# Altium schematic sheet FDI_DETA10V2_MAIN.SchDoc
size A4
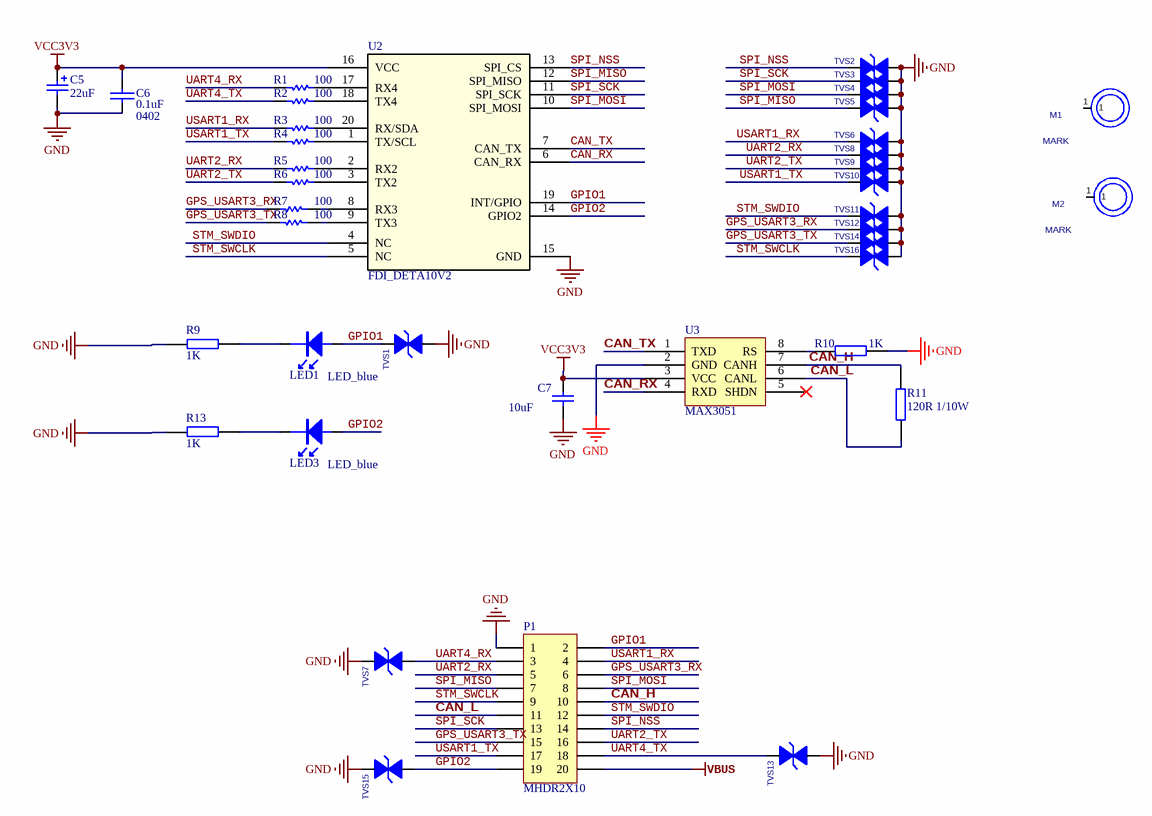
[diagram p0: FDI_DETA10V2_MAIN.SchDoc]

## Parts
C5  22uF  [C1206]
C6  Type: 0402  [C0402]  (hidden comment: 0.1uF)
C7  10uF  [C0603]
LED1  LED_blue  [LED_0603_BLUE]
LED3  LED_blue  [LED_0603_BLUE]
M1  MARK  [MARK_POINT]
M2  MARK  [MARK_POINT]
P1  MHDR2X10  [HEAD_2.54_20]
R1  100  [RES0402]
R2  100  [RES0402]
R3  100  [RES0402]
R4  100  [RES0402]
R5  100  [RES0402]
R6  100  [RES0402]
R7  100  [RES0402]
R8  100  [RES0402]
R9  1K  [RES0402]
R10  1K  [RES0402]
R11  120R 1/10W  [RES0603]
R13  1K  [RES0402]
TVS1  PTUC0521NC/5V  [ESD_0402]  (value not drawn)
TVS2  PTUC0521NC/5V  [ESD_0402]  (value not drawn)
TVS3  PTUC0521NC/5V  [ESD_0402]  (value not drawn)
TVS4  PTUC0521NC/5V  [ESD_0402]  (value not drawn)
TVS5  PTUC0521NC/5V  [ESD_0402]  (value not drawn)
TVS6  PTUC0521NC/5V  [ESD_0402]  (value not drawn)
TVS7  PTUC0521NC/5V  [ESD_0402]  (value not drawn)
TVS8  PTUC0521NC/5V  [ESD_0402]  (value not drawn)
TVS9  PTUC0521NC/5V  [ESD_0402]  (value not drawn)
TVS10  PTUC0521NC/5V  [ESD_0402]  (value not drawn)
TVS11  PTUC0521NC/5V  [ESD_0402]  (value not drawn)
TVS12  PTUC0521NC/5V  [ESD_0402]  (value not drawn)
TVS13  PTUC0521NC/5V  [ESD_0402]  (value not drawn)
TVS14  PTUC0521NC/5V  [ESD_0402]  (value not drawn)
TVS15  PTUC0521NC/5V  [ESD_0402]  (value not drawn)
TVS16  PTUC0521NC/5V  [ESD_0402]  (value not drawn)
U2  FDI_DETA10V2  [FDI_DETA]
U3  MAX3051  [SOT23-8]

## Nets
GND: C5.2 C6.1 C7.2 P1.1 R9.2 R10.1 R13.2 TVS1.2(I/O2) TVS2.2(I/O2) TVS3.2(I/O2) TVS4.2(I/O2) TVS5.2(I/O2) TVS6.2(I/O2) TVS7.1(I/O1) TVS8.2(I/O2) TVS9.2(I/O2) TVS10.2(I/O2) TVS11.2(I/O2) TVS12.2(I/O2) TVS13.2(I/O2) TVS14.2(I/O2) TVS15.1(I/O1) TVS16.2(I/O2) U2.15(GND) U3.2(GND)
VBUS: P1.20
VCC3V3: C5.1 C6.2 C7.1 U2.16(VCC) U3.3(VCC)
CAN_H: P1.10 R11.1 U3.7(CANH)
CAN_L: P1.11 R11.2 U3.6(CANL)
CAN_RX: U2.6(CAN_RX) U3.4(RXD)
CAN_TX: U2.7(CAN_TX) U3.1(TXD)
GPIO1: LED1.1 P1.2 TVS1.1(I/O1) U2.19(INT/GPIO)
GPIO2: LED3.1 P1.19 TVS15.2(I/O2) U2.14(GPIO2)
GPS_USART3_RX: P1.6 R7.2 TVS12.1(I/O1)
GPS_USART3_TX: P1.15 R8.2 TVS14.1(I/O1)
SPI_MISO: P1.7 TVS5.1(I/O1) U2.12(SPI_MISO)
SPI_MOSI: P1.8 TVS4.1(I/O1) U2.10(SPI_MOSI)
SPI_NSS: P1.14 TVS2.1(I/O1) U2.13(SPI_CS)
SPI_SCK: P1.13 TVS3.1(I/O1) U2.11(SPI_SCK)
STM_SWCLK: P1.9 TVS16.1(I/O1) U2.5(NC)
STM_SWDIO: P1.12 TVS11.1(I/O1) U2.4(NC)
UART2_RX: P1.5 R5.2 TVS8.1(I/O1)
UART2_TX: P1.16 R6.1 TVS9.1(I/O1)
UART4_RX: P1.3 R1.2 TVS7.2(I/O2)
UART4_TX: P1.18 R2.1 TVS13.1(I/O1)
USART1_RX: P1.4 R3.1 TVS6.1(I/O1)
USART1_TX: P1.17 R4.1 TVS10.1(I/O1)
NetLED1_2: LED1.2 R9.1
NetLED3_2: LED3.2 R13.1
NetR1_1: R1.1 U2.17(RX4)
NetR2_2: R2.2 U2.18(TX4)
NetR3_2: R3.2 U2.20(RX/SDA)
NetR4_2: R4.2 U2.1(TX/SCL)
NetR5_1: R5.1 U2.2(RX2)
NetR6_2: R6.2 U2.3(TX2)
NetR7_1: R7.1 U2.8(RX3)
NetR8_1: R8.1 U2.9(TX3)
NetR10_2: R10.2 U3.8(RS)

Not connected (* = marked no-connect by the designer): M1 1; M2 1; U3 5(SHDN)*

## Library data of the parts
C5 = Cap Pol1: Polarized Capacitor (Radial)
C6 = C1
C7 = CAP: Capacitor; Value: 100nF
LED1 LED3 = LED
M1 M2 = MARK: Photo Mark Point
P1 = MHDR2X10: Header, 10-Pin, Dual row
R1-R8 = Res1: Resistor; Value: 1K
R9-R11 R13 = R
TVS1-TVS16 = Varistor_0: 双向400瓦瞬态抑制器/5V; Part number: 110130100560; MFG: PTC
U3 = CAN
